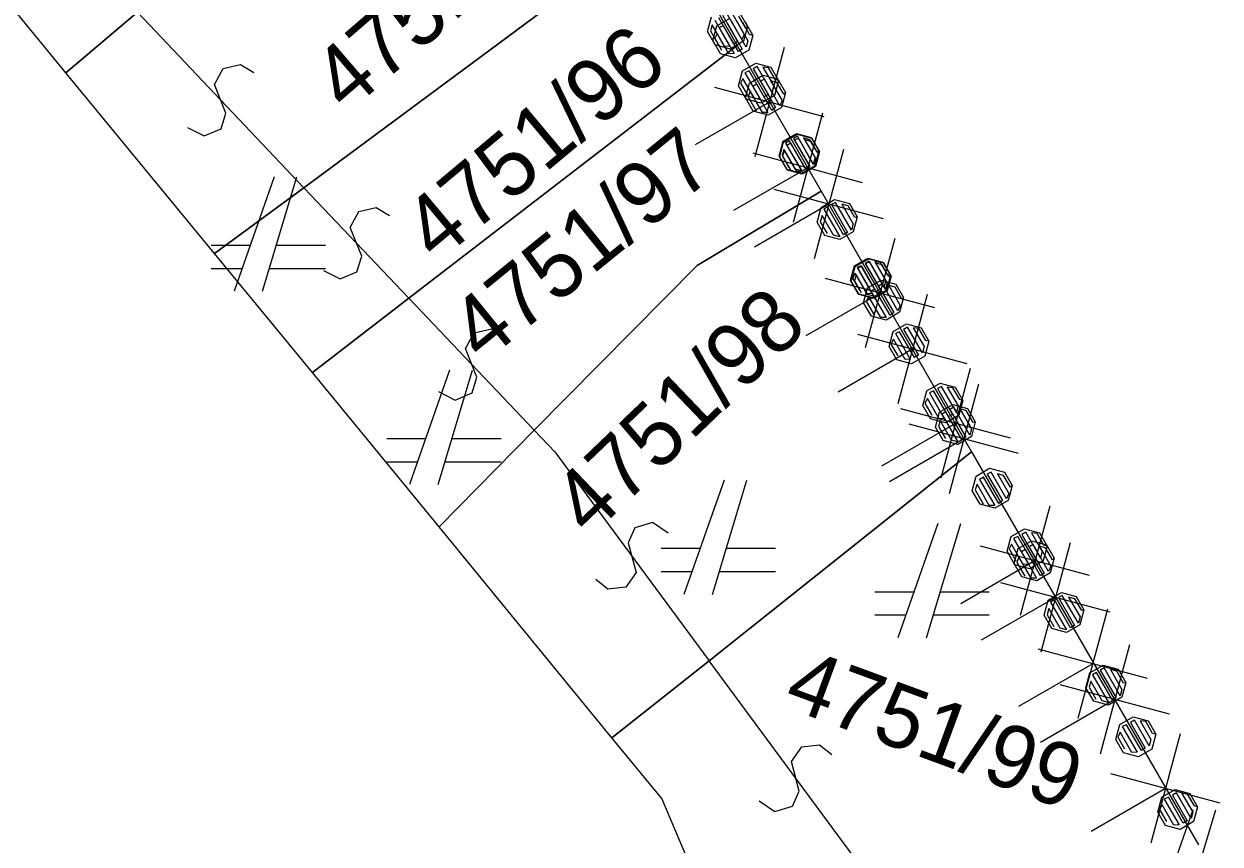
# Model space of a CAD drawing. Extents: x -266179 to -264727, y -1243225 to -1241702.
# Drawn here: x -264955.06 to -264934.14, y -1242265.42 to -1242251.07 of the extents above; entities that cross this region are included whole.
import ezdxf

# ---------------------------------------------------------------- set-up
doc = ezdxf.new("R2010")
doc.units = 0
for name, color, linetype in [('Vrstva 1', 7, 'Continuous'), ('Vrstva 19', 7, 'Continuous'), ('Vrstva 2', 7, 'Continuous'), ('Vrstva 21', 7, 'Continuous')]:
    doc.layers.add(name, color=color, linetype=linetype)

msp = doc.modelspace()

# ---------------------------------------------------------------- linework, layer by layer
at = {"layer": 'Vrstva 1'}
for p, q in [((-264954.33, -1242251.93), (-264958.21, -1242247.19)), ((-264950.17, -1242253.94), (-264943.85, -1242249.26)), ((-264943.85, -1242249.26), (-264950.17, -1242253.94)), ((-264943.85, -1242249.26), (-264942.59, -1242251.45)), ((-264954.33, -1242251.93), (-264953.08, -1242250.87)), ((-264953.08, -1242250.87), (-264954.33, -1242251.93)), ((-264948.33, -1242255.87), (-264942.59, -1242251.45)), ((-264942.59, -1242251.45), (-264948.33, -1242255.87)), ((-264942.59, -1242251.45), (-264941.12, -1242254)), ((-264951.73, -1242255.09), (-264954.33, -1242251.93)), ((-264951.73, -1242255.09), (-264950.17, -1242253.94)), ((-264950.17, -1242253.94), (-264951.73, -1242255.09)), ((-264950.69, -1242253.75), (-264951.39, -1242255.75)), ((-264950.89, -1242255.75), (-264950.29, -1242253.75)), ((-264943.29, -1242255.3), (-264941.12, -1242254)), ((-264941.12, -1242254), (-264943.29, -1242255.3)), ((-264941.12, -1242254), (-264938.49, -1242258.56)), ((-264951.11, -1242254.95), (-264951.79, -1242254.95)), ((-264949.79, -1242254.95), (-264950.65, -1242254.95)), ((-264950.02, -1242257.17), (-264951.73, -1242255.09)), ((-264951.79, -1242255.35), (-264951.25, -1242255.35)), ((-264950.77, -1242255.35), (-264949.79, -1242255.35)), ((-264946.14, -1242258.18), (-264943.29, -1242255.3)), ((-264943.29, -1242255.3), (-264946.14, -1242258.18)), ((-264950.02, -1242257.17), (-264948.33, -1242255.87)), ((-264948.33, -1242255.87), (-264950.02, -1242257.17)), ((-264947.8, -1242259.87), (-264950.02, -1242257.17)), ((-264947.62, -1242257.13), (-264948.32, -1242259.13)), ((-264947.82, -1242259.13), (-264947.22, -1242257.13)), ((-264948.04, -1242258.33), (-264948.72, -1242258.33)), ((-264947.8, -1242259.87), (-264946.14, -1242258.18)), ((-264946.14, -1242258.18), (-264947.8, -1242259.87)), ((-264946.72, -1242258.33), (-264947.58, -1242258.33)), ((-264948.72, -1242258.73), (-264948.18, -1242258.73)), ((-264947.7, -1242258.73), (-264946.72, -1242258.73)), ((-264943.08, -1242262.21), (-264938.49, -1242258.56)), ((-264938.49, -1242258.56), (-264943.08, -1242262.21)), ((-264938.49, -1242258.56), (-264934.52, -1242265.43)), ((-264942.82, -1242259.05), (-264943.52, -1242261.05)), ((-264943.02, -1242261.05), (-264942.42, -1242259.05)), ((-264944.78, -1242263.56), (-264947.8, -1242259.87)), ((-264939.08, -1242259.81), (-264939.78, -1242261.81)), ((-264939.28, -1242261.81), (-264938.68, -1242259.81)), ((-264943.24, -1242260.25), (-264943.92, -1242260.25)), ((-264941.92, -1242260.25), (-264942.78, -1242260.25)), ((-264943.92, -1242260.65), (-264943.38, -1242260.65)), ((-264942.9, -1242260.65), (-264941.92, -1242260.65)), ((-264939.5, -1242261.01), (-264940.18, -1242261.01)), ((-264938.18, -1242261.01), (-264939.04, -1242261.01)), ((-264940.18, -1242261.41), (-264939.64, -1242261.41)), ((-264939.16, -1242261.41), (-264938.18, -1242261.41)), ((-264944.78, -1242263.56), (-264943.08, -1242262.21)), ((-264943.08, -1242262.21), (-264944.78, -1242263.56)), ((-264943.91, -1242264.62), (-264944.78, -1242263.56)), ((-264943, -1242266.76), (-264943.91, -1242264.62)), ((-264934.62, -1242264.82), (-264935.32, -1242266.82)), ((-264934.82, -1242266.82), (-264934.22, -1242264.82))]:
    msp.add_line(p, q, dxfattribs=at)
at = {"layer": 'Vrstva 19'}
for p, q in [((-264943.85, -1242249.26), (-264942.59, -1242251.45)), ((-264942.59, -1242251.45), (-264941.12, -1242254)), ((-264941.12, -1242254), (-264938.49, -1242258.56)), ((-264938.49, -1242258.56), (-264934.52, -1242265.43))]:
    msp.add_line(p, q, dxfattribs=at)
for points in [[(-264942.41, -1242251.12), (-264942.48, -1242251.379), (-264942.714, -1242251.514), (-264942.973, -1242251.443), (-264943.108, -1242251.209), (-264943.038, -1242250.95)], [(-264942.98, -1242251.009), (-264942.716, -1242251.469), (-264942.811, -1242251.465), (-264943.025, -1242251.093), (-264943.059, -1242251.193), (-264942.92, -1242251.436)], [(-264942.317, -1242251.275), (-264942.387, -1242251.534), (-264942.621, -1242251.669), (-264942.88, -1242251.6), (-264943.015, -1242251.366), (-264942.946, -1242251.107), (-264942.712, -1242250.972)], [(-264942.847, -1242250.921), (-264942.583, -1242251.38), (-264942.647, -1242251.429), (-264942.911, -1242250.969)], [(-264942.668, -1242250.911), (-264942.469, -1242251.257), (-264942.508, -1242251.349), (-264942.777, -1242250.881)], [(-264942.544, -1242250.885), (-264942.41, -1242251.12), (-264942.439, -1242251.148), (-264942.559, -1242250.94)], [(-264942.76, -1242251.068), (-264942.5, -1242251.519), (-264942.569, -1242251.559), (-264942.829, -1242251.108), (-264942.903, -1242251.14), (-264942.643, -1242251.59), (-264942.733, -1242251.596), (-264942.938, -1242251.24), (-264942.982, -1242251.324), (-264942.862, -1242251.532)], [(-264942.591, -1242251.04), (-264942.401, -1242251.37), (-264942.43, -1242251.479), (-264942.69, -1242251.028)], [(-264942.452, -1242251.041), (-264942.317, -1242251.275), (-264942.372, -1242251.26), (-264942.492, -1242251.052)], [(-264941.867, -1242252.065), (-264941.937, -1242252.324), (-264942.171, -1242252.459), (-264942.431, -1242252.389), (-264942.565, -1242252.155), (-264942.495, -1242251.896), (-264942.262, -1242251.761), (-264942.002, -1242251.831), (-264941.867, -1242252.065), (-264941.922, -1242252.05), (-264942.042, -1242251.842), (-264942.141, -1242251.83), (-264941.951, -1242252.159), (-264941.981, -1242252.268), (-264942.24, -1242251.818), (-264942.31, -1242251.858), (-264942.05, -1242252.308), (-264942.119, -1242252.348), (-264942.379, -1242251.898), (-264942.453, -1242251.929), (-264942.194, -1242252.38), (-264942.283, -1242252.385), (-264942.488, -1242252.03), (-264942.532, -1242252.113), (-264942.412, -1242252.321)], [(-264941.746, -1242252.276), (-264941.816, -1242252.536), (-264942.049, -1242252.671), (-264942.309, -1242252.601), (-264942.444, -1242252.367), (-264942.374, -1242252.108), (-264942.141, -1242251.973), (-264941.881, -1242252.042), (-264941.746, -1242252.276), (-264941.776, -1242252.305), (-264941.896, -1242252.097), (-264942.005, -1242252.068), (-264941.805, -1242252.414), (-264941.844, -1242252.506), (-264942.114, -1242252.038), (-264942.184, -1242252.078), (-264941.919, -1242252.537), (-264941.983, -1242252.586), (-264942.248, -1242252.127), (-264942.317, -1242252.167), (-264942.052, -1242252.626), (-264942.146, -1242252.623), (-264942.361, -1242252.25), (-264942.396, -1242252.351), (-264942.256, -1242252.593)], [(-264941.159, -1242253.296), (-264941.229, -1242253.555), (-264941.463, -1242253.69), (-264941.722, -1242253.62), (-264941.857, -1242253.386), (-264941.787, -1242253.126), (-264941.553, -1242252.992), (-264941.293, -1242253.062), (-264941.159, -1242253.296), (-264941.199, -1242253.307), (-264941.318, -1242253.099), (-264941.427, -1242253.069), (-264941.228, -1242253.416), (-264941.258, -1242253.525), (-264941.537, -1242253.04), (-264941.606, -1242253.08), (-264941.327, -1242253.565), (-264941.396, -1242253.605), (-264941.675, -1242253.12), (-264941.745, -1242253.16), (-264941.466, -1242253.645), (-264941.575, -1242253.616), (-264941.774, -1242253.269), (-264941.804, -1242253.378), (-264941.684, -1242253.586)], [(-264941.148, -1242253.308), (-264941.218, -1242253.568), (-264941.452, -1242253.703), (-264941.712, -1242253.633), (-264941.846, -1242253.399), (-264941.777, -1242253.14), (-264941.543, -1242253.005), (-264941.283, -1242253.075), (-264941.148, -1242253.308), (-264941.178, -1242253.337), (-264941.298, -1242253.129), (-264941.407, -1242253.1), (-264941.207, -1242253.446), (-264941.247, -1242253.538), (-264941.516, -1242253.07), (-264941.586, -1242253.11), (-264941.321, -1242253.57), (-264941.385, -1242253.618), (-264941.65, -1242253.159), (-264941.719, -1242253.199), (-264941.455, -1242253.658), (-264941.549, -1242253.655), (-264941.764, -1242253.282), (-264941.798, -1242253.383), (-264941.658, -1242253.625)], [(-264940.491, -1242254.45), (-264940.561, -1242254.709), (-264940.794, -1242254.844), (-264941.054, -1242254.775), (-264941.189, -1242254.541), (-264941.119, -1242254.282), (-264940.886, -1242254.147), (-264940.626, -1242254.216), (-264940.491, -1242254.45), (-264940.531, -1242254.461), (-264940.651, -1242254.253), (-264940.76, -1242254.224), (-264940.56, -1242254.57), (-264940.589, -1242254.68), (-264940.869, -1242254.195), (-264940.939, -1242254.235), (-264940.659, -1242254.72), (-264940.728, -1242254.76), (-264941.008, -1242254.275), (-264941.077, -1242254.315), (-264940.797, -1242254.8), (-264940.906, -1242254.77), (-264941.106, -1242254.424), (-264941.136, -1242254.533), (-264941.016, -1242254.741)], [(-264939.908, -1242255.472), (-264939.978, -1242255.731), (-264940.212, -1242255.866), (-264940.472, -1242255.796), (-264940.606, -1242255.562), (-264940.536, -1242255.302), (-264940.302, -1242255.168), (-264940.043, -1242255.238), (-264939.908, -1242255.472), (-264939.963, -1242255.457), (-264940.082, -1242255.249), (-264940.182, -1242255.237), (-264939.992, -1242255.566), (-264940.022, -1242255.676), (-264940.281, -1242255.225), (-264940.35, -1242255.265), (-264940.091, -1242255.716), (-264940.161, -1242255.755), (-264940.42, -1242255.305), (-264940.494, -1242255.336), (-264940.235, -1242255.787), (-264940.324, -1242255.792), (-264940.529, -1242255.436), (-264940.573, -1242255.52), (-264940.453, -1242255.728)], [(-264939.896, -1242255.483), (-264939.965, -1242255.743), (-264940.199, -1242255.878), (-264940.459, -1242255.808), (-264940.594, -1242255.574), (-264940.524, -1242255.314), (-264940.29, -1242255.18), (-264940.03, -1242255.249), (-264939.896, -1242255.483), (-264939.935, -1242255.495), (-264940.055, -1242255.287), (-264940.164, -1242255.257), (-264939.965, -1242255.604), (-264939.994, -1242255.713), (-264940.273, -1242255.228), (-264940.343, -1242255.268), (-264940.063, -1242255.753), (-264940.133, -1242255.793), (-264940.412, -1242255.308), (-264940.481, -1242255.348), (-264940.202, -1242255.833), (-264940.311, -1242255.804), (-264940.511, -1242255.457), (-264940.54, -1242255.566), (-264940.42, -1242255.774)], [(-264939.68, -1242255.859), (-264939.749, -1242256.118), (-264939.983, -1242256.253), (-264940.243, -1242256.184), (-264940.378, -1242255.95), (-264940.308, -1242255.691), (-264940.074, -1242255.556), (-264939.815, -1242255.625), (-264939.68, -1242255.859), (-264939.709, -1242255.888), (-264939.829, -1242255.68), (-264939.939, -1242255.65), (-264939.739, -1242255.997), (-264939.778, -1242256.089), (-264940.048, -1242255.621), (-264940.117, -1242255.661), (-264939.852, -1242256.12), (-264939.916, -1242256.169), (-264940.181, -1242255.71), (-264940.251, -1242255.75), (-264939.986, -1242256.209), (-264940.08, -1242256.206), (-264940.295, -1242255.833), (-264940.329, -1242255.934), (-264940.189, -1242256.176)], [(-264939.236, -1242256.624), (-264939.306, -1242256.883), (-264939.539, -1242257.018), (-264939.799, -1242256.949), (-264939.934, -1242256.715), (-264939.864, -1242256.455), (-264939.631, -1242256.32), (-264939.371, -1242256.39), (-264939.236, -1242256.624), (-264939.291, -1242256.609), (-264939.411, -1242256.401), (-264939.51, -1242256.389), (-264939.32, -1242256.718), (-264939.349, -1242256.828), (-264939.609, -1242256.377), (-264939.679, -1242256.417), (-264939.419, -1242256.868), (-264939.488, -1242256.908), (-264939.748, -1242256.457), (-264939.822, -1242256.489), (-264939.562, -1242256.939), (-264939.651, -1242256.944), (-264939.856, -1242256.589), (-264939.901, -1242256.672), (-264939.781, -1242256.88)], [(-264938.643, -1242257.658), (-264938.712, -1242257.918), (-264938.946, -1242258.053), (-264939.206, -1242257.983), (-264939.341, -1242257.749), (-264939.271, -1242257.489), (-264939.037, -1242257.355), (-264938.777, -1242257.424), (-264938.643, -1242257.658), (-264938.697, -1242257.644), (-264938.817, -1242257.436), (-264938.916, -1242257.424), (-264938.727, -1242257.753), (-264938.756, -1242257.862), (-264939.016, -1242257.412), (-264939.085, -1242257.452), (-264938.825, -1242257.902), (-264938.895, -1242257.942), (-264939.154, -1242257.492), (-264939.229, -1242257.523), (-264938.969, -1242257.973), (-264939.058, -1242257.979), (-264939.263, -1242257.623), (-264939.307, -1242257.707), (-264939.188, -1242257.915)], [(-264938.425, -1242258.033), (-264938.494, -1242258.292), (-264938.728, -1242258.427), (-264938.988, -1242258.358), (-264939.123, -1242258.124), (-264939.053, -1242257.864), (-264938.819, -1242257.729), (-264938.56, -1242257.799), (-264938.425, -1242258.033), (-264938.464, -1242258.044), (-264938.584, -1242257.836), (-264938.694, -1242257.807), (-264938.494, -1242258.153), (-264938.523, -1242258.263), (-264938.803, -1242257.778), (-264938.872, -1242257.818), (-264938.592, -1242258.303), (-264938.661, -1242258.343), (-264938.941, -1242257.858), (-264939.011, -1242257.898), (-264938.731, -1242258.383), (-264938.84, -1242258.353), (-264939.04, -1242258.007), (-264939.069, -1242258.116), (-264938.949, -1242258.324)], [(-264937.779, -1242259.148), (-264937.849, -1242259.408), (-264938.083, -1242259.543), (-264938.342, -1242259.473), (-264938.477, -1242259.239), (-264938.408, -1242258.98), (-264938.174, -1242258.845), (-264937.915, -1242258.914), (-264937.779, -1242259.148), (-264937.809, -1242259.177), (-264937.929, -1242258.969), (-264938.038, -1242258.94), (-264937.838, -1242259.286), (-264937.878, -1242259.378), (-264938.148, -1242258.91), (-264938.217, -1242258.95), (-264937.952, -1242259.409), (-264938.016, -1242259.458), (-264938.281, -1242258.999), (-264938.351, -1242259.039), (-264938.086, -1242259.498), (-264938.18, -1242259.495), (-264938.395, -1242259.122), (-264938.429, -1242259.223), (-264938.289, -1242259.465)], [(-264937.17, -1242260.206), (-264937.239, -1242260.466), (-264937.473, -1242260.601), (-264937.733, -1242260.531), (-264937.868, -1242260.297), (-264937.798, -1242260.038), (-264937.564, -1242259.903), (-264937.305, -1242259.972), (-264937.17, -1242260.206), (-264937.224, -1242260.192), (-264937.344, -1242259.984), (-264937.444, -1242259.972), (-264937.254, -1242260.301), (-264937.283, -1242260.41), (-264937.543, -1242259.96), (-264937.612, -1242260), (-264937.352, -1242260.45), (-264937.421, -1242260.49), (-264937.681, -1242260.04), (-264937.756, -1242260.071), (-264937.496, -1242260.522), (-264937.585, -1242260.527), (-264937.79, -1242260.172), (-264937.834, -1242260.255), (-264937.714, -1242260.463)], [(-264937.046, -1242260.417), (-264937.116, -1242260.676), (-264937.35, -1242260.811), (-264937.609, -1242260.742), (-264937.744, -1242260.508), (-264937.675, -1242260.249), (-264937.441, -1242260.114), (-264937.181, -1242260.183), (-264937.046, -1242260.417), (-264937.076, -1242260.446), (-264937.196, -1242260.238), (-264937.305, -1242260.208), (-264937.105, -1242260.555), (-264937.145, -1242260.647), (-264937.415, -1242260.179), (-264937.484, -1242260.219), (-264937.219, -1242260.678), (-264937.283, -1242260.727), (-264937.548, -1242260.268), (-264937.617, -1242260.308), (-264937.352, -1242260.767), (-264937.447, -1242260.764), (-264937.662, -1242260.391), (-264937.696, -1242260.492), (-264937.556, -1242260.734)], [(-264936.524, -1242261.322), (-264936.594, -1242261.581), (-264936.828, -1242261.716), (-264937.087, -1242261.647), (-264937.222, -1242261.413), (-264937.153, -1242261.153), (-264936.919, -1242261.018), (-264936.659, -1242261.088), (-264936.524, -1242261.322), (-264936.564, -1242261.333), (-264936.684, -1242261.125), (-264936.793, -1242261.096), (-264936.593, -1242261.442), (-264936.623, -1242261.552), (-264936.903, -1242261.067), (-264936.972, -1242261.107), (-264936.692, -1242261.592), (-264936.761, -1242261.632), (-264937.041, -1242261.147), (-264937.111, -1242261.187), (-264936.831, -1242261.672), (-264936.94, -1242261.642), (-264937.14, -1242261.296), (-264937.169, -1242261.405), (-264937.049, -1242261.613)], [(-264935.791, -1242262.591), (-264935.861, -1242262.85), (-264936.095, -1242262.985), (-264936.354, -1242262.916), (-264936.489, -1242262.682), (-264936.42, -1242262.422), (-264936.186, -1242262.287), (-264935.926, -1242262.357), (-264935.791, -1242262.591), (-264935.831, -1242262.602), (-264935.951, -1242262.394), (-264936.06, -1242262.365), (-264935.86, -1242262.711), (-264935.889, -1242262.821), (-264936.169, -1242262.336), (-264936.239, -1242262.376), (-264935.959, -1242262.861), (-264936.028, -1242262.901), (-264936.308, -1242262.416), (-264936.377, -1242262.456), (-264936.097, -1242262.941), (-264936.207, -1242262.911), (-264936.407, -1242262.565), (-264936.436, -1242262.674), (-264936.316, -1242262.882)], [(-264935.269, -1242263.496), (-264935.339, -1242263.755), (-264935.573, -1242263.89), (-264935.832, -1242263.821), (-264935.967, -1242263.587), (-264935.898, -1242263.327), (-264935.664, -1242263.192), (-264935.404, -1242263.262), (-264935.269, -1242263.496), (-264935.324, -1242263.481), (-264935.444, -1242263.273), (-264935.543, -1242263.261), (-264935.353, -1242263.59), (-264935.383, -1242263.699), (-264935.643, -1242263.249), (-264935.712, -1242263.289), (-264935.452, -1242263.739), (-264935.521, -1242263.779), (-264935.781, -1242263.329), (-264935.855, -1242263.36), (-264935.595, -1242263.811), (-264935.685, -1242263.816), (-264935.89, -1242263.461), (-264935.934, -1242263.544), (-264935.814, -1242263.752)], [(-264934.536, -1242264.764), (-264934.606, -1242265.024), (-264934.84, -1242265.159), (-264935.099, -1242265.089), (-264935.234, -1242264.856), (-264935.165, -1242264.596), (-264934.931, -1242264.461), (-264934.671, -1242264.531), (-264934.536, -1242264.764), (-264934.591, -1242264.75), (-264934.711, -1242264.542), (-264934.81, -1242264.53), (-264934.62, -1242264.859), (-264934.649, -1242264.968), (-264934.909, -1242264.518), (-264934.979, -1242264.558), (-264934.719, -1242265.008), (-264934.788, -1242265.048), (-264935.048, -1242264.598), (-264935.122, -1242264.629), (-264934.862, -1242265.08), (-264934.952, -1242265.085), (-264935.157, -1242264.73), (-264935.201, -1242264.813), (-264935.081, -1242265.021)]]:
    msp.add_lwpolyline(points, dxfattribs=at)
at = {"layer": 'Vrstva 2'}
for p, q in [((-264950.17, -1242253.94), (-264953.08, -1242250.87)), ((-264948.33, -1242255.87), (-264950.17, -1242253.94)), ((-264946.14, -1242258.18), (-264948.33, -1242255.87)), ((-264946.14, -1242258.18), (-264945.78, -1242258.56)), ((-264945.78, -1242258.56), (-264943.08, -1242262.21)), ((-264940.06, -1242266.3), (-264943.08, -1242262.21))]:
    msp.add_line(p, q, dxfattribs=at)
for points in [[(-264952.204, -1242252.884), (-264951.911, -1242253.034), (-264951.617, -1242252.907), (-264951.532, -1242252.634), (-264951.731, -1242252.133), (-264951.582, -1242251.854), (-264951.276, -1242251.785), (-264951.046, -1242251.926)], [(-264949.827, -1242255.386), (-264949.534, -1242255.535), (-264949.241, -1242255.407), (-264949.157, -1242255.134), (-264949.357, -1242254.634), (-264949.208, -1242254.354), (-264948.903, -1242254.284), (-264948.673, -1242254.424)], [(-264947.813, -1242257.505), (-264947.52, -1242257.654), (-264947.227, -1242257.527), (-264947.142, -1242257.254), (-264947.341, -1242256.753), (-264947.192, -1242256.474), (-264946.886, -1242256.405), (-264946.657, -1242256.545)], [(-264943.797, -1242259.979), (-264944.07, -1242259.795), (-264944.377, -1242259.885), (-264944.494, -1242260.147), (-264944.358, -1242260.668), (-264944.54, -1242260.926), (-264944.852, -1242260.958), (-264945.063, -1242260.791)], [(-264942.203, -1242264.66), (-264941.93, -1242264.844), (-264941.624, -1242264.755), (-264941.506, -1242264.493), (-264941.642, -1242263.972), (-264941.46, -1242263.714), (-264941.148, -1242263.682), (-264940.937, -1242263.85)]]:
    msp.add_lwpolyline(points, dxfattribs=at)
at = {"layer": 'Vrstva 21'}
for p, q in [((-264943.85, -1242249.26), (-264942.59, -1242251.45)), ((-264942.59, -1242251.45), (-264941.12, -1242254)), ((-264941.767, -1242251.485), (-264942.28, -1242253.398)), ((-264941.067, -1242252.698), (-264942.98, -1242252.185)), ((-264942.023, -1242252.442), (-264943.322, -1242253.192)), ((-264941.096, -1242252.637), (-264941.613, -1242254.548)), ((-264940.73, -1242253.271), (-264941.242, -1242255.184)), ((-264940.399, -1242253.851), (-264942.31, -1242253.335)), ((-264941.354, -1242253.593), (-264942.655, -1242254.34)), ((-264940.03, -1242254.484), (-264941.942, -1242253.971)), ((-264941.12, -1242254), (-264938.49, -1242258.56)), ((-264940.986, -1242254.228), (-264942.285, -1242254.978)), ((-264939.834, -1242254.825), (-264940.349, -1242256.737)), ((-264939.135, -1242256.038), (-264941.047, -1242255.524)), ((-264940.091, -1242255.781), (-264941.391, -1242256.53)), ((-264939.267, -1242255.806), (-264939.779, -1242257.718)), ((-264938.567, -1242257.018), (-264940.479, -1242256.506)), ((-264939.523, -1242256.762), (-264940.822, -1242257.512)), ((-264938.512, -1242257.103), (-264939.025, -1242259.016)), ((-264938.368, -1242257.376), (-264938.88, -1242259.289)), ((-264937.812, -1242258.316), (-264939.725, -1242257.803)), ((-264938.769, -1242258.06), (-264940.068, -1242258.81)), ((-264937.668, -1242258.589), (-264939.58, -1242258.076)), ((-264938.624, -1242258.332), (-264939.923, -1242259.082)), ((-264938.49, -1242258.56), (-264934.52, -1242265.43)), ((-264937.124, -1242259.508), (-264937.638, -1242261.42)), ((-264936.425, -1242260.721), (-264938.337, -1242260.207)), ((-264936.767, -1242260.146), (-264937.28, -1242262.058)), ((-264937.381, -1242260.464), (-264938.681, -1242261.213)), ((-264936.067, -1242261.358), (-264937.98, -1242260.846)), ((-264937.023, -1242261.102), (-264938.322, -1242261.852)), ((-264936.114, -1242261.307), (-264936.63, -1242263.219)), ((-264935.416, -1242262.521), (-264937.327, -1242262.005)), ((-264935.73, -1242261.932), (-264936.243, -1242263.844)), ((-264936.372, -1242262.263), (-264937.672, -1242263.01)), ((-264935.03, -1242263.144), (-264936.943, -1242262.632)), ((-264935.987, -1242262.888), (-264937.286, -1242263.638)), ((-264934.843, -1242263.49), (-264935.357, -1242265.402)), ((-264934.144, -1242264.703), (-264936.056, -1242264.189)), ((-264935.1, -1242264.446), (-264936.4, -1242265.195))]:
    msp.add_line(p, q, dxfattribs=at)

# ---------------------------------------------------------------- texts
at = {"layer": 'Vrstva 1'}
for s, rotation, p in [('4751/95', 40.7946, (-264949.413, -1242252.652)), ('4751/96', 39.9352, (-264947.838, -1242255.268)), ('4751/97', 39.133, (-264947.034, -1242257.025)), ('4751/98', 43.774, (-264945.165, -1242260.069)), ('4751/99', 339.8213, (-264941.812, -1242263.001))]:
    msp.add_text(s, height=1.1, rotation=rotation, dxfattribs=at).set_placement(p)

doc.saveas('drawing.dxf')
